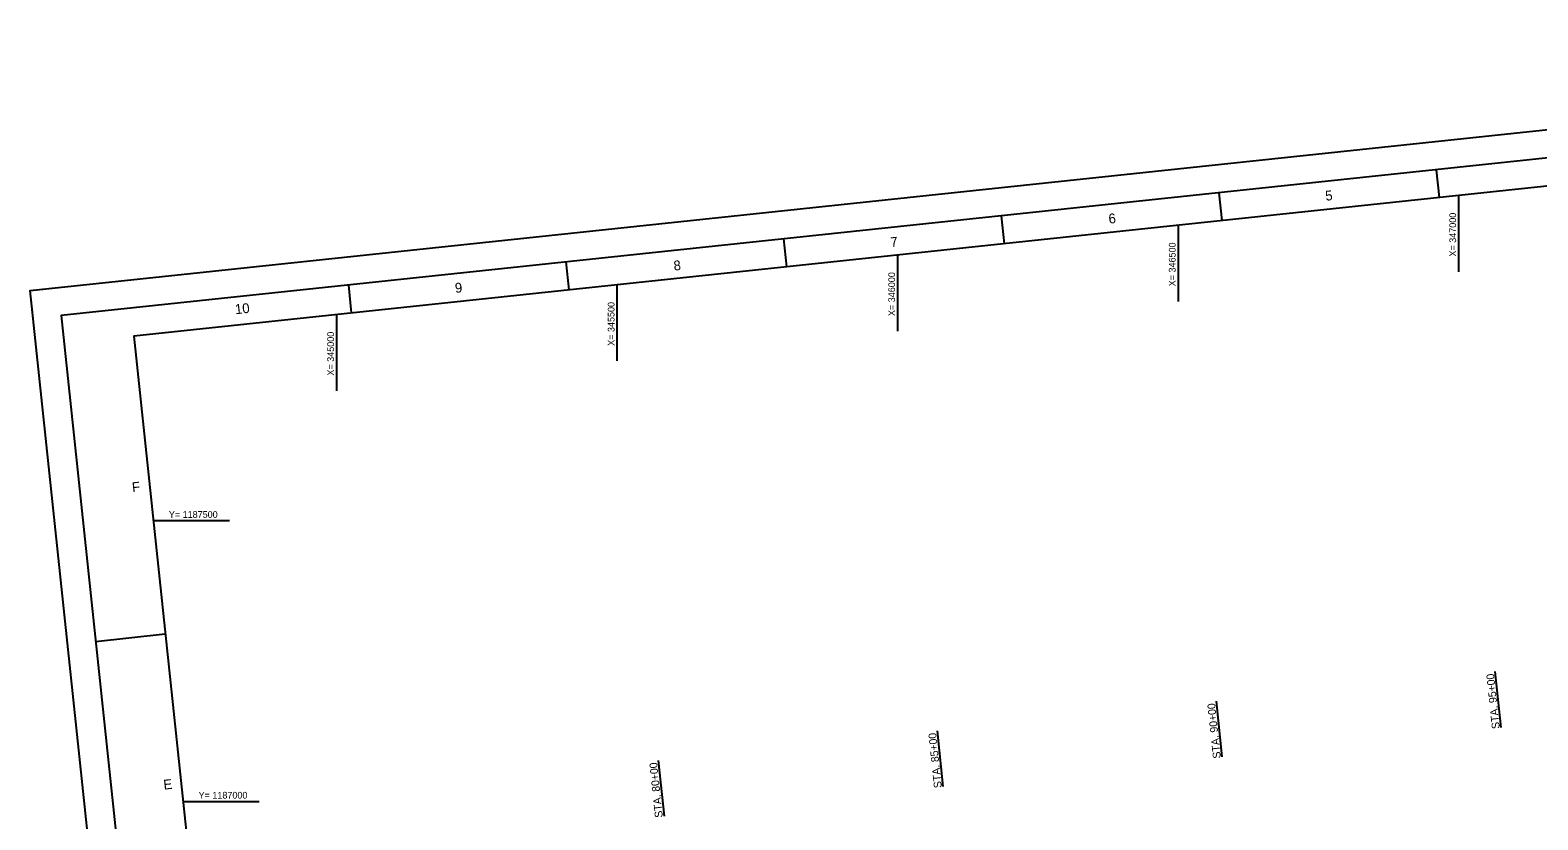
# Model space of a CAD drawing. Extents: x 344453 to 349187, y 1184529 to 1188374.
# Drawn here: x 344453 to 347141, y 1186967 to 1188374 of the extents above; entities that cross this region are included whole.
import ezdxf

# ---------------------------------------------------------------- set-up
doc = ezdxf.new("R2010")
doc.units = 0
for name, color, linetype in [('G-ANNO-NPLT', 7, 'Continuous'), ('G-ANNO-TTLB', 7, 'Continuous'), ('V-ALGN-TEXT', 7, 'Continuous'), ('V-TOPO-COOR-STAT', 7, 'Continuous')]:
    doc.layers.add(name, color=color, linetype=linetype)

msp = doc.modelspace()

# ---------------------------------------------------------------- linework, layer by layer
at = {"layer": 'G-ANNO-NPLT'}
msp.add_lwpolyline([(344453.5, 1187909.7), (348828.9, 1188373.5), (349187.3, 1184992.5), (344811.8, 1184528.7)], close=True, dxfattribs=at)
msp.add_lwpolyline([(344458.7, 1187860), (344453.5, 1187909.7), (344503.2, 1187915)], dxfattribs=at)
at = {"layer": 'G-ANNO-TTLB'}
for p, q in [((346959.7, 1188125.1), (346965, 1188075.4)), ((346571.9, 1188084), (346577.2, 1188034.3)), ((346184.1, 1188042.9), (346189.3, 1187993.2)), ((345796.2, 1188001.8), (345801.5, 1187952.1)), ((345408.4, 1187960.7), (345413.7, 1187911)), ((345408.4, 1187960.7), (345413.7, 1187911)), ((345020.6, 1187919.6), (345025.9, 1187869.9)), ((344570, 1187285), (344694.3, 1187298.2))]:
    msp.add_line(p, q, dxfattribs=at)
for points in [[(344856.3, 1184583.7), (349132.3, 1185036.9), (348784.5, 1188318.5), (344508.5, 1187865.3)], [(348740, 1188263.6), (344638, 1187828.7), (344975.3, 1184646.6), (349077.3, 1185081.4)]]:
    msp.add_lwpolyline(points, close=True, dxfattribs=at)
at = {"layer": 'V-ALGN-TEXT'}
for p, q in [((347075.5, 1187131.8), (347064.9, 1187231.2)), ((346578.3, 1187079.1), (346567.7, 1187178.5)), ((346081, 1187026.4), (346070.5, 1187125.8)), ((345583.8, 1186973.7), (345573.3, 1187073.1))]:
    msp.add_line(p, q, dxfattribs=at)
at = {"layer": 'V-TOPO-COOR-STAT'}
for p, q in [((347000, 1187943.4), (347000, 1188079.1)), ((346500, 1187890.4), (346500, 1188026.1)), ((346000, 1187837.4), (346000, 1187973.1)), ((345500, 1187784.4), (345500, 1187920.1)), ((345000, 1187731.4), (345000, 1187867.1)), ((344672.9, 1187500), (344808.6, 1187500)), ((344725.9, 1187000), (344861.6, 1187000))]:
    msp.add_line(p, q, dxfattribs=at)

# ---------------------------------------------------------------- texts
at = {"layer": 'G-ANNO-TTLB'}
for s, p in [('5', (346762.7, 1188069.7)), ('6', (346376.4, 1188028.8)), ('7', (345987.7, 1187986.9)), ('8', (345601.2, 1187945.2)), ('9', (345211.5, 1187905.5)), ('10', (344819.5, 1187867.6)), ('F', (344635.9, 1187550.6)), ('E', (344691.9, 1187020.9))]:
    msp.add_text(s, height=17.5, rotation=6.0506, dxfattribs=at).set_placement(p)
at = {"layer": 'V-ALGN-TEXT'}
for s, p in [('STA. 95+00', (347072.9, 1187129.8)), ('STA. 90+00', (346575.7, 1187077.1)), ('STA. 85+00', (346078.5, 1187024.4)), ('STA. 80+00', (345581.2, 1186971.7))]:
    msp.add_text(s, height=13.92, rotation=96.0506, dxfattribs=at).set_placement(p)
at = {"layer": 'V-TOPO-COOR-STAT'}
for s, p in [('X= 347000', (346995, 1187970.4)), ('X= 346500', (346495, 1187917.4)), ('X= 346000', (345995, 1187864.4)), ('X= 345500', (345495, 1187811.4)), ('X= 345000', (344995, 1187758.4))]:
    msp.add_text(s, height=12, rotation=90, dxfattribs=at).set_placement(p)
for s, p in [('Y= 1187500', (344700.7, 1187505)), ('Y= 1187000', (344753.7, 1187005))]:
    msp.add_text(s, height=12, dxfattribs=at).set_placement(p)

doc.saveas('drawing.dxf')
